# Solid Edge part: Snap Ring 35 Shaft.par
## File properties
Title: Snap Ring 35 Shaft
Author: Dan
Template: Normal.par
Last saved by: Dan
Revision: 9
Application: Solid Edge
Material: steel
Density: 0 kg/mm^3
Accuracy: 0.99
Document Number: P52-011
Project Name: Piston Pump P52
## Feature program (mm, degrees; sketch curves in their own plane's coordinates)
sketch for "unnamed Protrusion 1" plane through (0, 0, 0) normal (0, 0, 1) x-axis (1, 0, 0)
  line (-8.6805, 16.9012) -> (-8.6805, 14.9068)
  arc centre (0, 0) radius 17.25 from (8.6805, 14.9068) to (-8.6805, 14.9068) cw
  line (8.6805, 16.9012) -> (8.6805, 14.9068)
  arc centre (0, 0) radius 19 from (8.6805, 16.9012) to (-8.6805, 16.9012) cw
extrude "unnamed Protrusion 1" add finite 1.2 along +normal
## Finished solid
Body 1: solid body, 6 faces, 12 edges, 8 vertices.
  Faces by surface: plane 4, cylinder 2
  Edges by curve: line 8, circle 4
Bounding box of the edges (mm): 38.000 x 35.901 x 1.200, from (-19, -19, 0) to (19, 16.9012, 1.2).
Cylindrical faces by radius (mm): R17.25 x1, R19 x1
Planar faces by outward normal: +x 1, +z 1, -x 1, -z 1
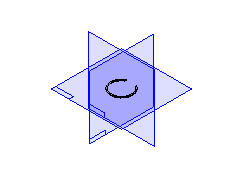
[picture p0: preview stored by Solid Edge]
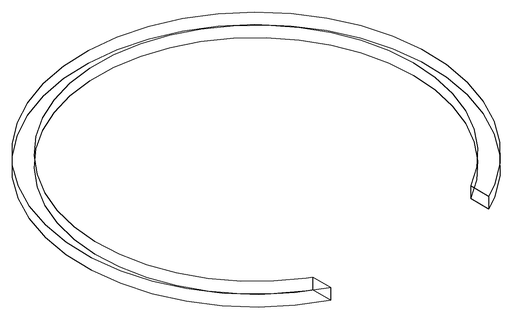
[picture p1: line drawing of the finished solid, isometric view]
